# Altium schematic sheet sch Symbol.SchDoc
size A4; Date: Not shown in title block; ApprovedBy: Not shown in title block; CheckedBy: Not shown in title block; Author: Not shown in title block; CompanyName: Not shown in title block; Engineer: Not shown in title block; Organization: Not shown in title block; Address1: Not shown in title block; Address2: Not shown in title block; Address3: Not shown in title block; Address4: Not shown in title block; DocumentNumber: 1; Revision: Use project parameter SCH_Rev; SheetNumber: 1; SheetTotal: 1; PageSetup: Record=PageOptions¦CenterHorizontal=True¦CenterVertical=True¦PrintScale=0.93¦XCorrection=1.00¦YCorrection=1.00¦PrintKind=0¦BorderSize=5000000¦LeftOffset=0¦BottomOffset=0¦Orientation=2¦PaperLength=1000¦PaperWidth=1000¦Scale=100¦PaperSource=15¦PrintQuality=600¦MediaType=1¦DitherType=10¦PaperKind=Letter¦PrintScaleMode=1
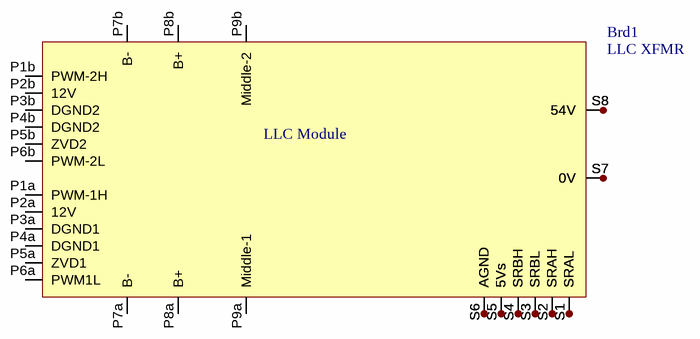
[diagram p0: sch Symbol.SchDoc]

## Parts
Brd1  LLC XFMR  [XFMR-PMP41114]

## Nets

Not connected (* = marked no-connect by the designer): Brd1 P1a(PWM-1H) P1b(PWM-2H) P2a(12V) P2b(12V) P3a(DGND1) P3b(DGND2) P4a(DGND1) P4b(DGND2) P5a(ZVD1) P5b(ZVD2) P6a(PWM1L) P6b(PWM-2L) P7a(B-) P7b(B-) P8a(B+) P8b(B+) P9a(Middle-1) P9b(Middle-2) S1(SRAL) S2(SRAH) S3(SRBL) S4(SRBH) S5(5Vs) S6(AGND) S7(0V) S8(54V)

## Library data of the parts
Brd1 = PMP41114_LLC_MODULE: 3.6kW 400V to 54V FB LLC Module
